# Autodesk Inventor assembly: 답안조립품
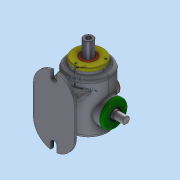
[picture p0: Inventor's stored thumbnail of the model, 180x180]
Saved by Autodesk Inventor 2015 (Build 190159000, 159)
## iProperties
Created: 2018-02
Part Number: 답안조립품
Document SubType Name: Assembly
Designer: SCD-A011
Author: SCD-A011
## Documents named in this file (16)
- C:\Users\SCD-A011\Desktop\380208v1002\답안조립품.iam
- C:\Users\SCD-A011\Desktop\380208v1002\가변스프링.ipt
- C:\Users\SCD-A011\Desktop\380208v1002\베어링 6205.ipt
- 베어링 6205.ipt
- C:\Users\SCD-A011\Desktop\380208v1002\본체.ipt
- C:\Users\SCD-A011\Desktop\380208v1002\본체커버.ipt
- C:\Users\SCD-A011\Desktop\380208v1002\볼트 M4.ipt
- C:\Users\SCD-A011\Desktop\380208v1002\부시.ipt
- C:\Users\SCD-A011\Desktop\380208v1002\상부 캡.ipt
- C:\Users\SCD-A011\Desktop\380208v1002\슬라이드 커버.ipt
- C:\Users\SCD-A011\Desktop\380208v1002\슬라이드.ipt
- C:\Users\SCD-A011\Desktop\380208v1002\오일실.ipt
- 오일실.ipt
- C:\Users\SCD-A011\Desktop\380208v1002\축 커버-1.ipt
- C:\Users\SCD-A011\Desktop\380208v1002\축 커버-2.ipt
- C:\Users\SCD-A011\Desktop\380208v1002\편심축.ipt
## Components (1 placed, 1 different names)
1. 가변스프링:1
